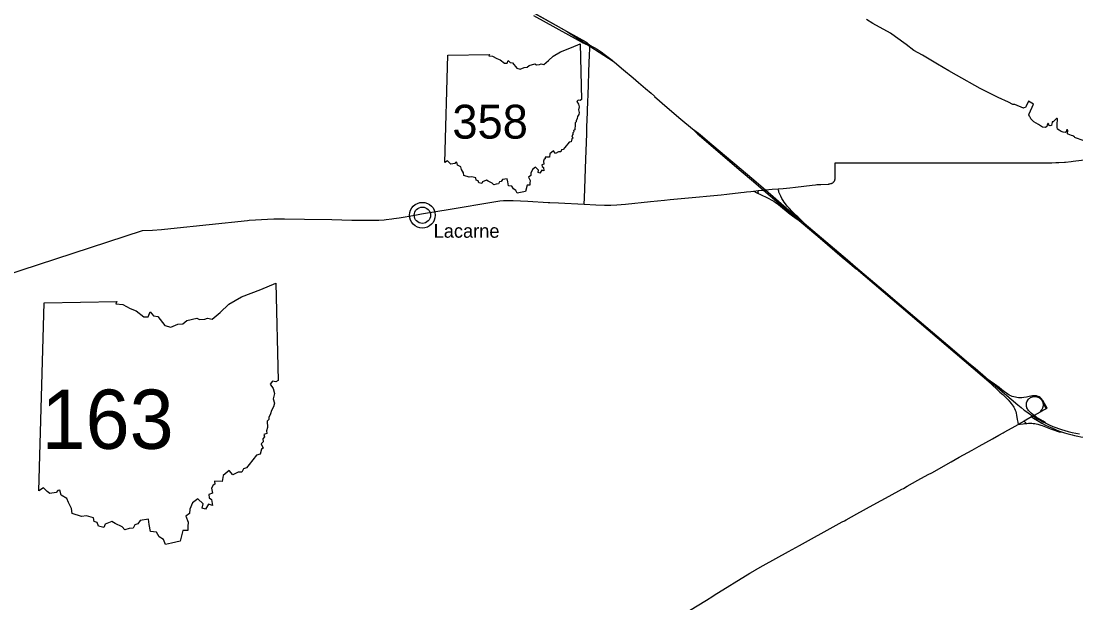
# Model space of a CAD drawing. Extents: x -82 to 873, y 0 to 440.
# Drawn here: x 319.9 to 400.6, y 147.6 to 192.1 of the extents above; entities that cross this region are included whole.
import ezdxf

# ---------------------------------------------------------------- set-up
doc = ezdxf.new("R2010")
doc.units = 0
for name, color, linetype in [('DV_X_Corp_Line', 7, 'Continuous'), ('GM_P_US_Alignment', 7, 'Continuous'), ('GM_X_County', 7, 'Continuous'), ('GM_X_Interchange_Ramps', 7, 'Continuous'), ('GM_X_Interstate_Route', 7, 'Continuous'), ('PV_P_Text', 7, 'Continuous')]:
    doc.layers.add(name, color=color, linetype=linetype)

msp = doc.modelspace()

# ---------------------------------------------------------------- linework, layer by layer
at = {"layer": 'DV_X_Corp_Line'}
for radius in [0.982, 0.623]:
    msp.add_circle((350.611, 177.279), radius, dxfattribs=at)
at = {"layer": 'GM_P_US_Alignment'}
msp.add_lwpolyline([(311.334, 247.708), (311.793, 241.068), (314.238, 236.419), (320.869, 225.952), (327.314, 216.112), (328.371, 214.651), (332.341, 212.251), (338.714, 207.336), (346.525, 202.192), (349.222, 200.826), (350.82, 199.691), (353.754, 196.704), (356.379, 194.294), (361.645, 191.348), (365.204, 189.06)], dxfattribs=at)
at = {"layer": 'GM_X_County'}
msp.add_lwpolyline([(401.134, 182.985), (400.549, 183.2), (400.51, 183.227), (400.482, 183.258), (400.42, 183.297), (400.361, 183.344), (400.248, 183.368), (399.998, 183.465), (399.952, 183.504), (399.932, 183.555), (399.956, 183.715), (399.959, 183.758), (399.936, 183.793), (399.885, 183.797), (399.858, 183.769), (399.834, 183.641), (399.764, 183.598), (399.608, 183.629), (399.464, 183.68), (399.312, 183.766), (399.183, 183.855), (399.148, 183.996), (399.155, 184.187), (399.171, 184.644), (399.144, 184.671), (399.097, 184.663), (398.839, 184.417), (398.8, 184.425), (398.765, 184.417), (398.765, 184.39), (398.777, 184.366), (398.73, 184.156), (398.718, 184.134), (398.625, 184.117), (398.543, 184.121), (398.512, 184.167), (398.512, 184.242), (398.465, 184.292), (398.43, 184.292), (398.391, 184.148), (398.352, 184.046), (398.262, 183.98), (398.032, 184.015), (397.712, 184.202), (397.372, 184.409), (397.134, 184.651), (397.122, 184.725), (397.087, 184.768), (397.032, 184.823), (396.996, 184.938), (397.007, 185.016), (397.333, 185.776), (396.954, 185.99), (396.763, 185.553), (396.72, 185.502), (396.608, 185.482), (396.587, 185.464), (395.904, 185.746), (395.76, 185.748), (395.428, 185.904), (394.645, 186.265), (393.274, 186.971), (391.448, 187.976), (390.862, 188.311), (389.996, 188.814), (388.849, 189.497), (388.201, 189.868), (387.604, 190.317), (386.802, 190.914), (386.396, 191.197), (385.067, 191.936), (384.564, 192.229)], dxfattribs=at)
at = {"layer": 'GM_X_Interchange_Ramps'}
for points in [[(375.94, 179.117), (375.968, 179.103), (376.147, 179.013), (376.296, 178.936), (376.417, 178.873), (377.041, 178.57), (377.334, 178.424), (377.477, 178.344), (377.615, 178.256), (377.749, 178.161), (378.007, 177.96), (378.735, 177.369), (378.817, 177.304), (379.185, 177.02), (379.264, 176.973), (379.414, 176.882)], [(376.306, 179.158), (376.291, 179.142), (376.285, 179.131), (376.281, 179.122), (376.276, 179.105), (376.271, 179.09), (376.268, 179.069), (376.266, 179.051), (376.266, 179.031), (376.268, 179.012), (376.271, 179), (376.278, 178.98), (376.296, 178.936)], [(379.813, 176.677), (379.534, 176.955), (379.424, 177.061), (379.32, 177.157), (379.196, 177.264), (379.045, 177.405), (378.87, 177.579), (378.672, 177.789), (378.508, 177.975), (378.378, 178.135), (378.28, 178.268), (378.19, 178.406), (378.107, 178.549), (378.012, 178.732), (377.942, 178.881), (377.895, 178.995), (377.88, 179.039), (377.857, 179.112), (377.832, 179.2), (377.812, 179.284), (377.809, 179.296)], [(398.392, 162.528), (398.181, 162.894), (398.06, 163.109), (398.016, 163.178), (397.966, 163.243), (397.908, 163.302), (397.844, 163.353), (397.775, 163.397), (397.7, 163.432), (397.622, 163.457), (397.582, 163.467), (397.501, 163.478), (397.419, 163.481), (397.337, 163.476), (397.255, 163.465), (397.013, 163.416), (396.812, 163.376), (396.609, 163.343), (396.445, 163.326), (396.322, 163.322), (396.199, 163.327), (396.076, 163.341), (395.956, 163.365), (395.844, 163.392), (395.72, 163.433), (395.605, 163.481), (395.494, 163.534), (395.387, 163.596), (395.284, 163.665), (395.119, 163.785), (394.926, 163.934), (394.714, 164.102), (394.367, 164.37), (394.041, 164.598), (393.927, 164.674)], [(394.104, 164.394), (394.207, 164.279), (394.513, 164), (394.776, 163.758), (394.991, 163.565), (395.2, 163.366), (395.402, 163.159), (395.541, 163.007), (395.647, 162.881), (395.722, 162.782), (395.792, 162.68), (395.834, 162.609), (395.892, 162.5), (395.94, 162.386), (395.981, 162.27), (396.015, 162.151), (396.05, 161.989), (396.103, 161.664), (396.134, 161.46), (396.16, 161.284)], [(398.273, 161.388), (398.232, 161.439), (398.17, 161.488), (398.081, 161.539), (397.905, 161.639), (397.728, 161.741), (397.555, 161.85), (397.389, 161.97), (397.289, 162.042), (397.163, 162.147), (397.047, 162.262), (396.965, 162.353), (396.916, 162.418), (396.874, 162.489), (396.841, 162.563), (396.828, 162.602), (396.817, 162.642), (396.809, 162.682), (396.804, 162.722), (396.801, 162.763), (396.801, 162.804), (396.804, 162.844), (396.809, 162.885), (396.817, 162.925), (396.841, 163.003), (396.873, 163.079), (396.893, 163.114), (396.915, 163.149), (396.965, 163.214), (396.993, 163.243), (397.023, 163.271), (397.054, 163.297), (397.088, 163.32), (397.123, 163.342), (397.159, 163.361), (397.196, 163.377), (397.235, 163.392), (397.274, 163.404), (397.314, 163.413), (397.354, 163.42), (397.395, 163.425), (397.436, 163.427), (397.476, 163.426), (397.517, 163.423), (397.558, 163.416), (397.597, 163.408), (397.637, 163.396), (397.675, 163.382), (397.713, 163.366), (397.749, 163.347), (397.784, 163.326), (397.818, 163.303), (397.85, 163.277), (397.88, 163.25), (397.935, 163.189), (397.959, 163.157), (398.001, 163.086), (398.035, 163.012), (398.052, 162.962), (398.061, 162.934), (398.076, 162.854), (398.079, 162.813), (398.079, 162.773), (398.077, 162.732), (398.072, 162.691), (398.063, 162.651), (398.052, 162.612), (398.023, 162.535), (398.002, 162.489), (397.975, 162.436), (397.941, 162.379), (397.887, 162.293), (397.843, 162.225)], [(398.035, 163.012), (398.323, 162.49)], [(396.63, 161.547), (396.673, 161.484), (396.716, 161.423), (396.764, 161.362)]]:
    msp.add_lwpolyline(points, dxfattribs=at)
at = {"layer": 'GM_X_Interstate_Route'}
msp.add_line((394.104, 164.394), (383.773, 173.174), dxfattribs=at)
for points in [[(358.776, 192.945), (361.645, 191.348), (363.113, 190.527), (363.204, 190.464), (363.247, 190.426), (363.416, 190.265)], [(359.116, 192.545), (362.525, 190.645), (362.887, 190.446), (362.998, 190.389), (363.119, 190.339), (363.416, 190.265)], [(362.986, 178.114), (362.987, 178.139), (363.001, 178.58), (363.11, 181.572), (363.128, 182.187), (363.176, 183.498), (363.198, 184.113), (363.207, 184.482), (363.261, 185.998), (363.279, 186.449), (363.368, 188.99), (363.384, 189.433), (363.391, 189.628), (363.398, 189.724), (363.405, 189.812), (363.413, 189.907), (363.42, 189.974), (363.426, 190.026), (363.428, 190.071), (363.428, 190.116), (363.426, 190.164), (363.422, 190.217), (363.416, 190.265)], [(363.416, 190.265), (363.657, 190.135), (363.797, 190.062), (363.966, 189.967), (364.121, 189.872), (364.281, 189.765), (364.516, 189.596), (364.821, 189.365), (365.134, 189.118), (365.204, 189.06)], [(365.204, 189.06), (365.293, 188.985), (365.98, 188.399), (366.733, 187.764), (367.137, 187.417), (367.67, 186.965), (368.101, 186.597), (368.363, 186.364), (368.369, 186.359)], [(368.369, 186.359), (369.328, 185.512), (370.385, 184.612), (371.256, 183.87)], [(371.256, 183.87), (371.666, 183.481), (371.793, 183.365), (374.983, 180.653), (375.921, 179.852), (376.529, 179.336)], [(371.256, 183.87), (371.735, 183.541), (371.854, 183.45), (372.747, 182.69), (375.467, 180.376), (376.124, 179.817), (376.844, 179.213), (378.643, 177.674), (379.685, 176.787), (379.813, 176.677), (383.108, 173.877), (383.74, 173.34), (385.866, 171.532), (386.928, 170.627), (391.306, 166.903), (392.372, 166.001), (392.871, 165.574), (393.675, 164.889), (393.927, 164.674), (396.148, 162.778), (396.4, 162.568), (396.629, 162.386), (396.82, 162.245), (397.034, 162.094), (397.197, 161.988), (397.303, 161.921), (397.453, 161.831), (397.632, 161.726), (397.844, 161.608), (398.059, 161.495), (398.273, 161.388), (398.551, 161.258), (398.826, 161.139), (399.046, 161.052), (399.261, 160.975), (399.481, 160.901), (399.739, 160.821), (400.002, 160.75), (400.291, 160.677), (400.572, 160.617), (400.855, 160.564)], [(394.324, 181.283), (394.891, 181.285), (395.268, 181.287), (396.745, 181.286), (398.657, 181.288), (398.722, 181.288), (398.756, 181.288), (399.051, 181.296), (399.289, 181.302), (399.711, 181.331), (399.78, 181.335), (400.229, 181.381), (400.364, 181.4), (401.002, 181.486), (401.245, 181.519), (401.68, 181.583)], [(380.43, 179.576), (380.669, 179.604), (380.769, 179.613), (380.923, 179.625), (381.078, 179.636), (381.629, 179.654), (381.683, 179.657), (381.728, 179.663), (381.773, 179.669), (381.851, 179.689), (381.89, 179.703), (381.926, 179.719), (381.955, 179.736), (381.994, 179.76), (382.02, 179.78), (382.04, 179.798), (382.058, 179.816), (382.079, 179.839), (382.095, 179.857), (382.109, 179.876), (382.126, 179.899), (382.14, 179.925), (382.149, 179.946), (382.154, 179.962), (382.159, 179.982), (382.163, 180.007), (382.167, 180.036), (382.169, 180.064), (382.176, 180.181), (382.178, 180.96), (382.177, 181.125), (382.178, 181.289)], [(382.178, 181.289), (383.119, 181.287), (385.458, 181.285), (387.634, 181.285), (390.907, 181.285), (391.946, 181.286)], [(391.946, 181.286), (392.559, 181.286), (392.84, 181.285), (392.974, 181.285), (393.298, 181.284), (393.572, 181.282), (393.79, 181.281), (394.324, 181.283)], [(373.472, 178.844), (373.897, 178.885), (374.956, 179.005), (375.221, 179.035), (375.405, 179.056), (375.72, 179.093), (375.94, 179.117), (376.306, 179.158), (376.577, 179.188), (376.622, 179.193)], [(376.529, 179.336), (376.68, 179.207), (376.69, 179.199), (379.414, 176.882), (380.211, 176.205), (381.023, 175.514), (382.709, 174.079), (382.988, 173.841), (383.773, 173.174)], [(376.622, 179.193), (376.69, 179.199), (376.844, 179.213), (377.354, 179.26), (377.809, 179.296), (378.198, 179.327), (378.712, 179.379), (379.156, 179.424), (380.43, 179.576)], [(329.206, 176.101), (329.977, 176.143), (330.66, 176.187), (331.365, 176.253), (337.232, 176.875), (337.365, 176.889), (337.856, 176.931), (338.758, 176.981), (339.25, 176.995), (340.071, 176.993), (341.59, 176.968), (343.683, 176.937), (345.226, 176.909), (346.104, 176.893), (346.719, 176.887), (347.235, 176.903), (347.293, 176.905), (347.702, 176.935), (347.845, 176.952), (348.272, 177), (348.436, 177.024), (348.84, 177.083), (350.041, 177.286), (350.55, 177.371), (352.726, 177.738), (356.085, 178.304), (356.533, 178.365), (356.82, 178.389), (357.149, 178.398), (357.56, 178.39), (358.667, 178.339), (360.23, 178.259), (360.366, 178.252), (361.013, 178.218), (362.986, 178.114)], [(362.986, 178.114), (363.884, 178.067), (364.54, 178.046), (364.725, 178.043), (365.032, 178.047), (365.483, 178.062), (366.137, 178.115), (368.055, 178.319), (369.136, 178.426), (369.566, 178.469), (370.686, 178.577), (373.472, 178.844)], [(304.096, 169.345), (304.151, 169.351), (305.55, 169.5), (307.915, 169.767), (308.732, 169.858), (309.139, 169.903), (310.241, 170.028), (310.746, 170.084), (312.24, 170.248), (312.811, 170.314), (313.218, 170.367), (313.419, 170.402), (313.499, 170.419), (313.696, 170.474), (313.89, 170.537), (314.121, 170.623), (314.538, 170.794), (315.283, 171.105), (316.237, 171.518), (317.441, 172.079), (317.985, 172.336), (318.616, 172.632), (329.206, 176.101)], [(398.392, 162.528), (398.323, 162.49), (398.11, 162.373), (397.843, 162.225), (397.389, 161.97), (397.303, 161.921), (397.194, 161.861), (396.63, 161.547), (396.16, 161.284)], [(396.16, 161.284), (396.315, 161.298), (396.54, 161.328), (396.655, 161.346), (396.764, 161.362), (396.82, 161.368), (396.957, 161.378), (397.079, 161.381), (397.226, 161.375), (397.326, 161.365), (397.44, 161.353), (397.547, 161.333), (397.676, 161.303), (397.817, 161.261), (397.911, 161.232), (398.004, 161.198), (398.638, 160.956), (398.872, 160.871), (399.217, 160.752), (399.303, 160.732), (399.363, 160.724), (399.422, 160.719), (399.489, 160.719)], [(397.194, 161.861), (397.34, 161.765), (397.646, 161.577), (397.982, 161.379), (397.992, 161.374)], [(397.992, 161.374), (398.264, 161.232), (398.498, 161.119), (398.732, 161.014), (399.019, 160.896), (399.256, 160.804), (399.489, 160.719)], [(394.679, 160.457), (395.016, 160.645)], [(395.016, 160.645), (395.109, 160.697), (395.709, 161.033)], [(395.709, 161.033), (396.16, 161.284)], [(399.489, 160.719), (399.717, 160.644), (399.902, 160.589), (400.098, 160.534), (400.289, 160.484), (400.489, 160.435), (400.723, 160.387), (400.955, 160.345), (401.191, 160.31), (401.446, 160.277), (401.72, 160.246), (402.023, 160.221), (402.326, 160.211), (402.71, 160.208), (403.294, 160.216), (406.132, 160.28), (407.078, 160.297), (408.155, 160.319), (409.151, 160.34)], [(371.036, 147.074), (372.329, 147.867), (372.818, 148.169), (372.923, 148.233), (375.651, 149.91), (375.66, 149.916), (376.048, 150.148), (376.073, 150.163), (376.682, 150.509), (378.62, 151.578), (379.446, 152.035), (380.129, 152.411), (381.567, 153.205), (382.716, 153.833), (382.898, 153.929), (383.005, 153.989), (383.831, 154.447), (385.091, 155.138), (386.315, 155.808), (387.275, 156.33), (387.394, 156.394), (387.692, 156.56), (388.506, 157.014), (389.292, 157.45), (389.559, 157.599), (391.051, 158.433), (391.66, 158.774), (392.662, 159.332), (393.2, 159.631), (394.206, 160.193)], [(394.206, 160.193), (394.679, 160.457)]]:
    msp.add_lwpolyline(points, dxfattribs=at)
at = {"layer": 'PV_P_Text'}
for p, q in [((352.32, 181.301), (352.549, 189.508)), ((352.32, 181.301), (352.549, 189.508)), ((321.285, 156.217), (321.685, 170.58)), ((321.285, 156.217), (321.685, 170.58))]:
    msp.add_line(p, q, dxfattribs=at)
for points in [[(352.549, 189.508), (355.733, 189.562), (355.683, 189.462), (355.984, 189.442), (356.303, 189.266), (356.573, 189.156), (356.903, 188.895), (357.101, 188.898), (357.184, 189.112), (357.336, 188.947), (357.515, 188.917), (357.826, 188.524), (358.082, 188.439), (358.389, 188.574), (358.618, 188.596), (358.786, 188.729), (359.223, 188.843), (359.345, 188.775), (359.576, 188.789), (359.692, 188.839), (359.894, 188.794), (360.249, 189.092), (360.615, 189.444), (361.177, 189.776), (362.017, 190.091), (362.682, 190.372), (362.778, 186.113)], [(352.549, 189.508), (355.733, 189.562), (355.683, 189.462), (355.984, 189.442), (356.303, 189.266), (356.573, 189.156), (356.903, 188.895), (357.101, 188.898), (357.184, 189.112), (357.336, 188.947), (357.515, 188.917), (357.826, 188.524), (358.082, 188.439), (358.389, 188.574), (358.618, 188.596), (358.786, 188.729), (359.223, 188.843), (359.345, 188.775), (359.576, 188.789), (359.692, 188.839), (359.894, 188.794), (360.249, 189.092), (360.615, 189.444), (361.177, 189.776), (362.017, 190.091), (362.682, 190.372), (362.778, 186.113)], [(362.778, 186.113), (362.68, 186.053), (362.527, 186.082), (362.425, 185.962), (362.552, 185.763), (362.612, 185.552), (362.559, 185.32), (362.611, 185.129), (362.575, 184.968), (362.479, 184.809), (362.446, 184.657), (362.365, 184.497), (362.372, 184.407), (362.294, 184.336), (362.308, 184.07), (362.269, 183.922), (362.282, 183.795), (362.156, 183.762), (362.185, 183.656), (362.105, 183.575), (362.122, 183.435), (362.031, 183.346), (362.119, 183.167), (362.049, 183.111), (361.99, 182.893), (361.828, 182.849), (361.504, 182.452), (361.39, 182.302), (361.261, 182.264), (361.191, 182.11), (361.033, 182.109), (360.794, 182.002), (360.639, 182.186), (360.368, 181.965), (360.337, 181.709), (359.994, 181.717), (360.008, 181.587), (359.931, 181.55), (359.862, 181.42), (359.902, 181.19), (359.742, 181.131), (359.761, 180.997), (359.864, 180.916), (359.909, 180.66), (359.739, 180.712), (359.599, 180.496), (359.456, 180.547), (359.503, 180.729), (359.26, 180.949), (359.031, 180.773), (358.911, 180.492), (358.91, 180.303), (358.739, 180.189), (358.848, 179.922), (358.828, 179.738), (358.832, 179.564), (358.618, 179.57), (358.489, 179.099)], [(362.778, 186.113), (362.68, 186.053), (362.527, 186.082), (362.425, 185.962), (362.552, 185.763), (362.612, 185.552), (362.559, 185.32), (362.611, 185.129), (362.575, 184.968), (362.479, 184.809), (362.446, 184.657), (362.365, 184.497), (362.372, 184.407), (362.294, 184.336), (362.308, 184.07), (362.269, 183.922), (362.282, 183.795), (362.156, 183.762), (362.185, 183.656), (362.105, 183.575), (362.122, 183.435), (362.031, 183.346), (362.119, 183.167), (362.049, 183.111), (361.99, 182.893), (361.828, 182.849), (361.504, 182.452), (361.39, 182.302), (361.261, 182.264), (361.191, 182.11), (361.033, 182.109), (360.794, 182.002), (360.639, 182.186), (360.368, 181.965), (360.337, 181.709), (359.994, 181.717), (360.008, 181.587), (359.931, 181.55), (359.862, 181.42), (359.902, 181.19), (359.742, 181.131), (359.761, 180.997), (359.864, 180.916), (359.909, 180.66), (359.739, 180.712), (359.599, 180.496), (359.456, 180.547), (359.503, 180.729), (359.26, 180.949), (359.031, 180.773), (358.911, 180.492), (358.91, 180.303), (358.739, 180.189), (358.848, 179.922), (358.828, 179.738), (358.832, 179.564), (358.618, 179.57), (358.489, 179.099)], [(358.489, 179.099), (358.117, 179.009), (357.859, 178.955), (357.768, 179.169), (357.583, 179.281), (357.463, 179.497), (357.198, 179.526), (357.136, 179.822), (357.106, 180.062), (356.744, 180.003), (356.644, 179.856), (356.516, 179.817), (356.442, 179.669), (356.266, 179.656), (356.079, 179.587), (355.956, 179.732), (355.648, 179.877), (355.509, 179.953), (355.22, 179.836), (355.158, 179.698), (354.928, 179.759), (354.874, 179.913), (354.734, 179.959), (354.704, 180.122), (354.406, 180.209), (354.178, 180.175), (353.776, 180.306), (353.751, 180.521), (353.614, 180.783), (353.543, 180.965), (353.289, 181.104), (353.237, 181.321), (353.156, 181.314), (353.082, 181.226), (352.799, 181.186), (352.687, 181.275), (352.529, 181.425), (352.32, 181.301)], [(358.489, 179.099), (358.117, 179.009), (357.859, 178.955), (357.768, 179.169), (357.583, 179.281), (357.463, 179.497), (357.198, 179.526), (357.136, 179.822), (357.106, 180.062), (356.744, 180.003), (356.644, 179.856), (356.516, 179.817), (356.442, 179.669), (356.266, 179.656), (356.079, 179.587), (355.956, 179.732), (355.648, 179.877), (355.509, 179.953), (355.22, 179.836), (355.158, 179.698), (354.928, 179.759), (354.874, 179.913), (354.734, 179.959), (354.704, 180.122), (354.406, 180.209), (354.178, 180.175), (353.776, 180.306), (353.751, 180.521), (353.614, 180.783), (353.543, 180.965), (353.289, 181.104), (353.237, 181.321), (353.156, 181.314), (353.082, 181.226), (352.799, 181.186), (352.687, 181.275), (352.529, 181.425), (352.32, 181.301)], [(321.685, 170.58), (327.258, 170.674), (327.171, 170.5), (327.697, 170.464), (328.256, 170.157), (328.728, 169.964), (329.306, 169.507), (329.652, 169.512), (329.798, 169.887), (330.062, 169.598), (330.377, 169.546), (330.92, 168.859), (331.368, 168.71), (331.905, 168.946), (332.307, 168.984), (332.6, 169.217), (333.365, 169.416), (333.578, 169.297), (333.983, 169.321), (334.187, 169.409), (334.54, 169.331), (335.162, 169.853), (335.801, 170.469), (336.785, 171.05), (338.256, 171.6), (339.418, 172.093), (339.587, 164.639)], [(321.685, 170.58), (327.258, 170.674), (327.171, 170.5), (327.697, 170.464), (328.256, 170.157), (328.728, 169.964), (329.306, 169.507), (329.652, 169.512), (329.798, 169.887), (330.062, 169.598), (330.377, 169.546), (330.92, 168.859), (331.368, 168.71), (331.905, 168.946), (332.307, 168.984), (332.6, 169.217), (333.365, 169.416), (333.578, 169.297), (333.983, 169.321), (334.187, 169.409), (334.54, 169.331), (335.162, 169.853), (335.801, 170.469), (336.785, 171.05), (338.256, 171.6), (339.418, 172.093), (339.587, 164.639)], [(339.587, 164.639), (339.415, 164.535), (339.148, 164.584), (338.968, 164.375), (339.191, 164.026), (339.296, 163.658), (339.203, 163.252), (339.294, 162.917), (339.232, 162.636), (339.064, 162.357), (339.006, 162.091), (338.864, 161.811), (338.876, 161.654), (338.739, 161.53), (338.764, 161.063), (338.695, 160.805), (338.719, 160.582), (338.498, 160.524), (338.549, 160.34), (338.409, 160.198), (338.439, 159.953), (338.279, 159.797), (338.434, 159.484), (338.31, 159.385), (338.207, 159.005), (337.924, 158.927), (337.357, 158.232), (337.157, 157.969), (336.933, 157.903), (336.809, 157.633), (336.532, 157.632), (336.114, 157.445), (335.843, 157.767), (335.369, 157.379), (335.314, 156.932), (334.715, 156.946), (334.738, 156.719), (334.605, 156.653), (334.483, 156.427), (334.553, 156.023), (334.273, 155.921), (334.307, 155.687), (334.487, 155.543), (334.567, 155.096), (334.268, 155.187), (334.024, 154.81), (333.773, 154.898), (333.855, 155.218), (333.431, 155.602), (333.029, 155.294), (332.819, 154.803), (332.817, 154.472), (332.518, 154.272), (332.71, 153.805), (332.675, 153.483), (332.681, 153.178), (332.306, 153.189), (332.08, 152.364)], [(339.587, 164.639), (339.415, 164.535), (339.148, 164.584), (338.968, 164.375), (339.191, 164.026), (339.296, 163.658), (339.203, 163.252), (339.294, 162.917), (339.232, 162.636), (339.064, 162.357), (339.006, 162.091), (338.864, 161.811), (338.876, 161.654), (338.739, 161.53), (338.764, 161.063), (338.695, 160.805), (338.719, 160.582), (338.498, 160.524), (338.549, 160.34), (338.409, 160.198), (338.439, 159.953), (338.279, 159.797), (338.434, 159.484), (338.31, 159.385), (338.207, 159.005), (337.924, 158.927), (337.357, 158.232), (337.157, 157.969), (336.933, 157.903), (336.809, 157.633), (336.532, 157.632), (336.114, 157.445), (335.843, 157.767), (335.369, 157.379), (335.314, 156.932), (334.715, 156.946), (334.738, 156.719), (334.605, 156.653), (334.483, 156.427), (334.553, 156.023), (334.273, 155.921), (334.307, 155.687), (334.487, 155.543), (334.567, 155.096), (334.268, 155.187), (334.024, 154.81), (333.773, 154.898), (333.855, 155.218), (333.431, 155.602), (333.029, 155.294), (332.819, 154.803), (332.817, 154.472), (332.518, 154.272), (332.71, 153.805), (332.675, 153.483), (332.681, 153.178), (332.306, 153.189), (332.08, 152.364)], [(332.08, 152.364), (331.43, 152.206), (330.978, 152.112), (330.819, 152.487), (330.496, 152.684), (330.286, 153.061), (329.822, 153.112), (329.713, 153.63), (329.661, 154.051), (329.027, 153.947), (328.853, 153.69), (328.628, 153.621), (328.498, 153.362), (328.191, 153.34), (327.863, 153.218), (327.647, 153.472), (327.109, 153.727), (326.867, 153.858), (326.36, 153.654), (326.252, 153.412), (325.849, 153.519), (325.754, 153.788), (325.51, 153.869), (325.456, 154.155), (324.935, 154.308), (324.536, 154.247), (323.833, 154.477), (323.79, 154.854), (323.55, 155.312), (323.425, 155.631), (322.98, 155.874), (322.89, 156.253), (322.748, 156.241), (322.618, 156.088), (322.124, 156.017), (321.927, 156.172), (321.65, 156.436), (321.285, 156.217)], [(332.08, 152.364), (331.43, 152.206), (330.978, 152.112), (330.819, 152.487), (330.496, 152.684), (330.286, 153.061), (329.822, 153.112), (329.713, 153.63), (329.661, 154.051), (329.027, 153.947), (328.853, 153.69), (328.628, 153.621), (328.498, 153.362), (328.191, 153.34), (327.863, 153.218), (327.647, 153.472), (327.109, 153.727), (326.867, 153.858), (326.36, 153.654), (326.252, 153.412), (325.849, 153.519), (325.754, 153.788), (325.51, 153.869), (325.456, 154.155), (324.935, 154.308), (324.536, 154.247), (323.833, 154.477), (323.79, 154.854), (323.55, 155.312), (323.425, 155.631), (322.98, 155.874), (322.89, 156.253), (322.748, 156.241), (322.618, 156.088), (322.124, 156.017), (321.927, 156.172), (321.65, 156.436), (321.285, 156.217)]]:
    msp.add_lwpolyline(points, dxfattribs=at)

# ---------------------------------------------------------------- texts
at = {"layer": 'DV_X_Corp_Line'}
msp.add_text('Lacarne', height=1.0417, rotation=0.00501, dxfattribs=at).set_placement((351.475, 175.555))
at = {"layer": 'PV_P_Text'}
for s, height, p in [('358', 2.5875, (352.907, 183.131)), ('163', 4.5281, (321.492, 159.42))]:
    msp.add_text(s, height=height, rotation=0.005, dxfattribs=at).set_placement(p)

doc.saveas('drawing.dxf')
